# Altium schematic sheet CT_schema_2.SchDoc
size 365 x 192 mm
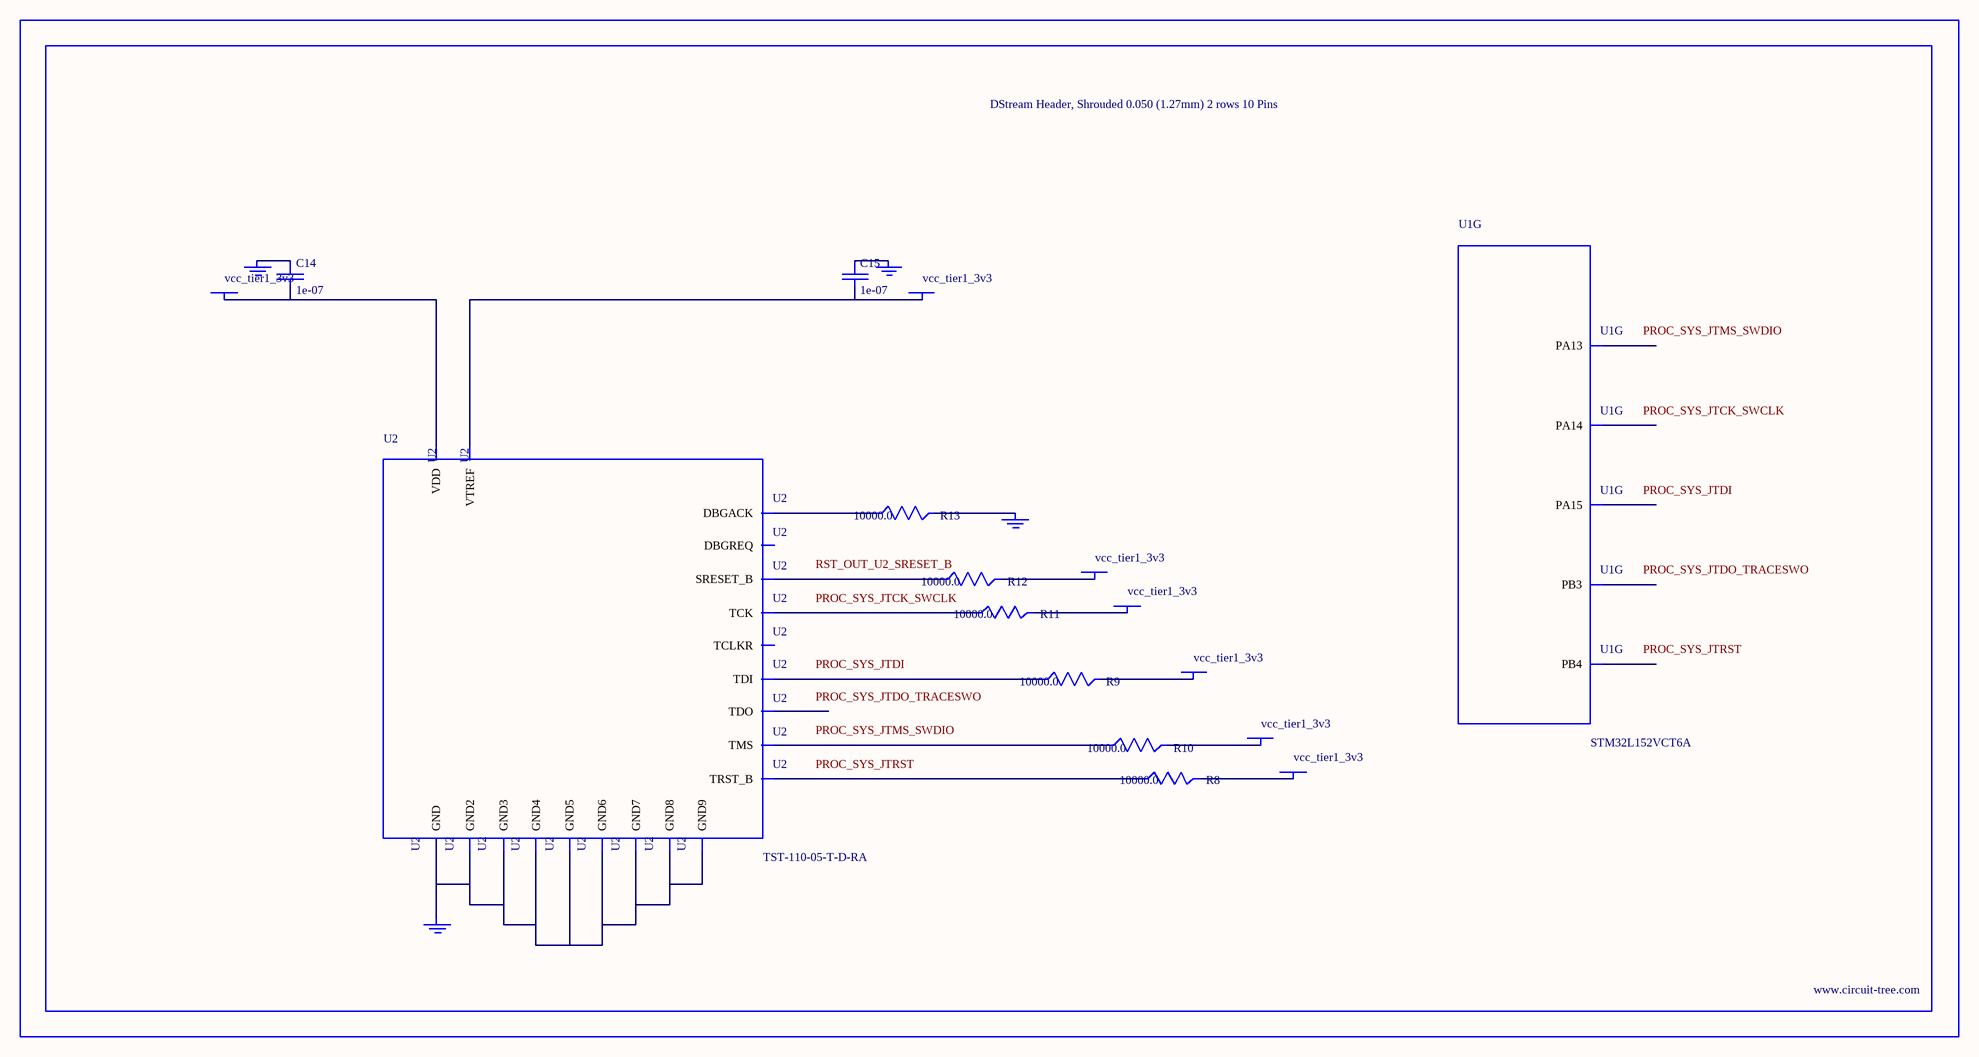
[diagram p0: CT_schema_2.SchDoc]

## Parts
BORDER1  (no value)
C14  1e-07  [C0402]
C15  1e-07  [C0402]
GND_INSTANCE_1_0  (no value)
GND_INSTANCE_1_1  (no value)
GND_INSTANCE_1_2  (no value)
GND_INSTANCE_1_3  (no value)
POWER_INSTANCE_1_0  vcc_tier1_3v3
POWER_INSTANCE_1_1  vcc_tier1_3v3
POWER_INSTANCE_1_2  vcc_tier1_3v3
POWER_INSTANCE_1_3  vcc_tier1_3v3
POWER_INSTANCE_1_4  vcc_tier1_3v3
POWER_INSTANCE_1_5  vcc_tier1_3v3
POWER_INSTANCE_1_6  vcc_tier1_3v3
R8  10000.0  [R0603]
R9  10000.0  [R0603]
R10  10000.0  [R0603]
R11  10000.0  [R0603]
R12  10000.0  [R0603]
R13  10000.0  [R0603]
U1  STM32L152VCT6A  [LQFP100]  (part G of 9)
U2  TST-110-05-T-D-RA  [TST-110-05-T-D-RA]

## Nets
NetC14_1: C14.1 GND_INSTANCE_1_1.0(GND)
NetC14_2: C14.2 POWER_INSTANCE_1_1.0(PWR) U2.2(VDD)
NetC15_1: C15.1 GND_INSTANCE_1_0.0(GND)
NetC15_2: C15.2 POWER_INSTANCE_1_0.0(PWR) U2.1(VTREF)
NetGND_INSTANCE_1_2_0: GND_INSTANCE_1_2.0(GND) R13.2
NetGND_INSTANCE_1_3_0: GND_INSTANCE_1_3.0(GND) U2.4(GND) U2.6(GND2) U2.8(GND3) U2.10(GND4) U2.12(GND5) U2.14(GND6) U2.16(GND7) U2.18(GND8) U2.20(GND9)
NetPOWER_INSTANCE_1_2_0: POWER_INSTANCE_1_2.0(PWR) R8.2
NetPOWER_INSTANCE_1_3_0: POWER_INSTANCE_1_3.0(PWR) R9.2
NetPOWER_INSTANCE_1_4_0: POWER_INSTANCE_1_4.0(PWR) R10.2
NetPOWER_INSTANCE_1_5_0: POWER_INSTANCE_1_5.0(PWR) R11.2
NetPOWER_INSTANCE_1_6_0: POWER_INSTANCE_1_6.0(PWR) R12.2
NetR8_1: R8.1 U2.3(TRST_B)
NetR9_1: R9.1 U2.5(TDI)
NetR10_1: R10.1 U2.7(TMS)
NetR11_1: R11.1 U2.9(TCK)
NetR12_1: R12.1 U2.15(SRESET_B)
NetR13_1: R13.1 U2.19(DBGACK)

Not connected (* = marked no-connect by the designer): U1 72(PA13) 76(PA14) 77(PA15) 89(PB3) 90(PB4); U2 11(TCLKR) 13(TDO) 17(DBGREQ)

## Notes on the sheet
- Labels drawn without touching a wire or pin: PROC_SYS_JTCK_SWCLK, PROC_SYS_JTDI, PROC_SYS_JTDO_TRACESWO, PROC_SYS_JTMS_SWDIO, PROC_SYS_JTRST, RST_OUT_U2_SRESET_B

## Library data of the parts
BORDER1 = BORDER_PAGE1
C14 C15 = C0402C104K3RACTU
GND_INSTANCE_1_0-GND_INSTANCE_1_3 = GND
POWER_INSTANCE_1_0-POWER_INSTANCE_1_6 = PWR
R8-R13 = RC0603JR-0710KL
